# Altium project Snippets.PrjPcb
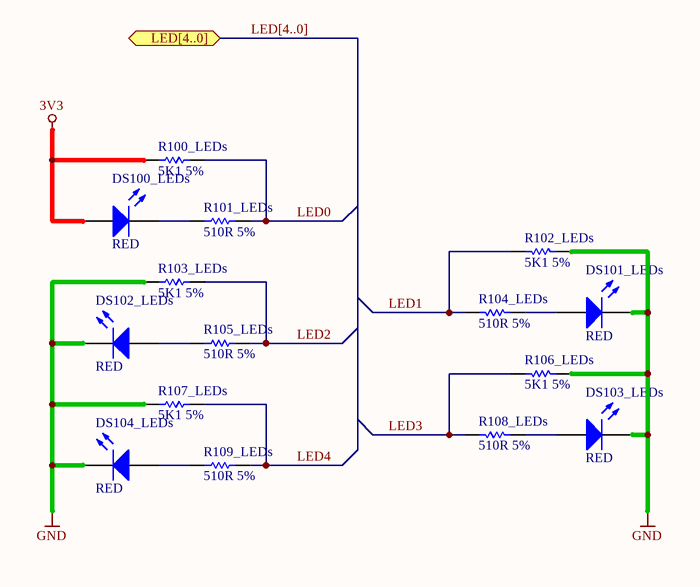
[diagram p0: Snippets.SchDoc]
1 sheet, 15 parts. Net scope: flat (ports and power ports of the same name join across sheets).
Board file: Snippets.PcbDoc

## Sheet Snippets.SchDoc: Snippets
size 431 x 279 mm; SheetNumber: 1; SheetTotal: 1

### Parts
DS100_LEDs  RED  [LED2013]
DS101_LEDs  RED  [LED2013]
DS102_LEDs  RED  [LED2013]
DS103_LEDs  RED  [LED2013]
DS104_LEDs  RED  [LED2013]
R100_LEDs  5K1 5%  [RESC2012]
R101_LEDs  510R 5%  [RESC2012]
R102_LEDs  5K1 5%  [RESC2012]
R103_LEDs  5K1 5%  [RESC2012]
R104_LEDs  510R 5%  [RESC2012]
R105_LEDs  510R 5%  [RESC2012]
R106_LEDs  5K1 5%  [RESC2012]
R107_LEDs  5K1 5%  [RESC2012]
R108_LEDs  510R 5%  [RESC2012]
R109_LEDs  510R 5%  [RESC2012]

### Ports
LED[4..0] (bidir)

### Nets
3V3: DS100_LEDs.1(A) R100_LEDs.1
GND: DS101_LEDs.2(K) DS102_LEDs.2(K) DS103_LEDs.2(K) DS104_LEDs.2(K) R102_LEDs.1 R103_LEDs.1 R106_LEDs.1 R107_LEDs.1
LED0: R100_LEDs.2 R101_LEDs.2
LED1: R102_LEDs.2 R104_LEDs.2
LED2: R103_LEDs.2 R105_LEDs.2
LED3: R106_LEDs.2 R108_LEDs.2
LED4: R107_LEDs.2 R109_LEDs.2
NetDS100_LEDs_2: DS100_LEDs.2(K) R101_LEDs.1
NetDS101_LEDs_1: DS101_LEDs.1(A) R104_LEDs.1
NetDS102_LEDs_1: DS102_LEDs.1(A) R105_LEDs.1
NetDS103_LEDs_1: DS103_LEDs.1(A) R108_LEDs.1
NetDS104_LEDs_1: DS104_LEDs.1(A) R109_LEDs.1

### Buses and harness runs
bus LED[4..0] = port LED[4..0]

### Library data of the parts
DS100_LEDs DS101_LEDs DS102_LEDs DS103_LEDs DS104_LEDs = DIO-LED-1S: Typical GREEN SMD LED Agilent make
R100_LEDs R101_LEDs R102_LEDs R103_LEDs R104_LEDs R105_LEDs R106_LEDs R107_LEDs R108_LEDs R109_LEDs = RES: Resistor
